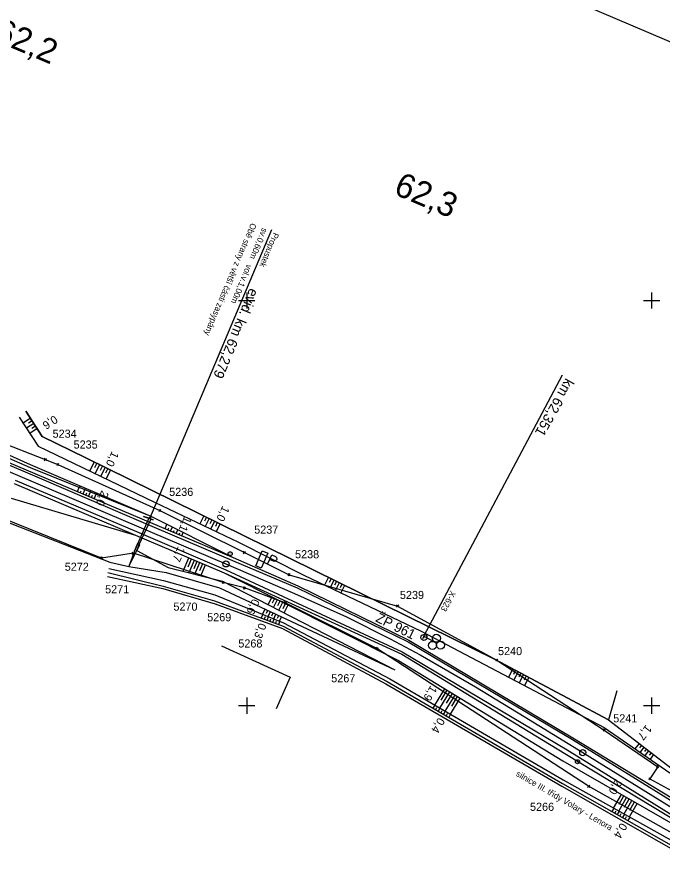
# Model space of a CAD drawing. Extents: x -805636 to -804553, y -1165340 to -1164656.
# Drawn here: x -805256.7 to -805097.2, y -1165040.5 to -1164830.1 of the extents above; entities that cross this region are included whole.
import ezdxf

# ---------------------------------------------------------------- set-up
doc = ezdxf.new("R2010")
doc.units = 0
for name, color, linetype in [('0381KM061-064P - Vrstva 1', 7, 'Continuous'), ('0381KM061-064P - Vrstva 17', 7, 'Continuous'), ('0381KM061-064P - Vrstva 19', 7, 'Continuous'), ('0381KM061-064P - Vrstva 23', 7, 'Continuous'), ('0381KM061-064P - Vrstva 33', 7, 'Continuous'), ('0381KM061-064P - Vrstva 4', 7, 'Continuous'), ('0381KM061-064P - Vrstva 48', 7, 'Continuous'), ('0381KM061-064P - Vrstva 49', 7, 'Continuous'), ('0381KM061-064P - Vrstva 51', 7, 'Continuous'), ('0381KM061-064P - Vrstva 7', 7, 'Continuous'), ('0381KM061-064P - Vrstva 8', 7, 'Continuous'), ('formát', 7, 'Continuous'), ('krizky_1000 - Vrstva 1', 7, 'Continuous'), ('szdc - hran DP', 7, 'Continuous'), ('szdc - szdc_cislo', 7, 'Continuous'), ('szdc - szdc_krizek', 7, 'Continuous'), ('vyt_sit - stávající', 7, 'Continuous')]:
    doc.layers.add(name, color=color, linetype=linetype)

msp = doc.modelspace()

# ---------------------------------------------------------------- linework, layer by layer
at = {"layer": '0381KM061-064P - Vrstva 1'}
for points in [[(-805344.65, -1164905.78), (-805313.66, -1164918.88), (-805286.17, -1164930.55), (-805256.63, -1164943.09), (-805230.48, -1164954.2), (-805205.12, -1164965.01), (-805202.66, -1164966.06)], [(-805202.66, -1164966.06), (-805188.16, -1164972.33), (-805175.38, -1164978.12)], [(-805175.38, -1164978.12), (-805164.58, -1164983.51), (-805157.2, -1164987.48)], [(-805157.2, -1164987.48), (-805143.51, -1164995.39), (-805131.47, -1165002.7)], [(-805131.47, -1165002.7), (-805117.01, -1165011.6), (-805094.55, -1165025.46), (-805076.19, -1165036.77)]]:
    msp.add_lwpolyline(points, dxfattribs=at)
at = {"layer": '0381KM061-064P - Vrstva 17'}
msp.add_lwpolyline([(-805108.59, -1164996.37), (-805110.66, -1165003.53), (-805138.64, -1164988.6), (-805160.38, -1164977.95), (-805217.98, -1164949.5), (-805239.73, -1164938.85), (-805250.48, -1164933.58), (-805254.52, -1164927.32)], dxfattribs=at)
at = {"layer": '0381KM061-064P - Vrstva 19'}
msp.add_line((-805223.94, -1164953.85), (-805193.79, -1164882.51), dxfattribs=at)
for points in [[(-805225.46, -1164953.29), (-805223.07, -1164954.18)], [(-805223.07, -1164954.18), (-805223.66, -1164953.94), (-805223.66, -1164953.95), (-805224.21, -1164953.74), (-805224.2, -1164953.73), (-805225.46, -1164953.29), (-805225.46, -1164953.29)], [(-805224.2, -1164953.73), (-805226.95, -1164960.17)], [(-805223.66, -1164953.94), (-805226.63, -1164960.32)], [(-805226.95, -1164960.17), (-805227.7, -1164961.91), (-805226.89, -1164959.92)], [(-805226.63, -1164960.32), (-805227.14, -1164961.71), (-805226.51, -1164960.3)], [(-805226.95, -1164960.17), (-805226.89, -1164959.92), (-805226.51, -1164960.3), (-805226.63, -1164960.32)]]:
    msp.add_lwpolyline(points, dxfattribs=at)
at = {"layer": '0381KM061-064P - Vrstva 23'}
msp.add_lwpolyline([(-805206.24, -1164985.26), (-805189.29, -1164992.96), (-805192.75, -1165000.8)], dxfattribs=at)
at = {"layer": '0381KM061-064P - Vrstva 33'}
msp.add_lwpolyline([(-805196.16, -1164961.8), (-805194.79, -1164962.4), (-805196.4, -1164966.09), (-805197.77, -1164965.49)], close=True, dxfattribs=at)
for points in [[(-805194.83, -1164965.11), (-805193.83, -1164962.81)], [(-805193.37, -1164964.36), (-805194.33, -1164963.94)], [(-805193.83, -1164962.81), (-805192.88, -1164963.22)], [(-805192.88, -1164963.22), (-805192.63, -1164963.45), (-805192.59, -1164963.91), (-805192.68, -1164964.11), (-805193.04, -1164964.4), (-805193.37, -1164964.36)]]:
    msp.add_lwpolyline(points, dxfattribs=at)
at = {"layer": '0381KM061-064P - Vrstva 4'}
for points in [[(-805364.7, -1164895.97), (-805343.19, -1164904.86), (-805317.03, -1164915.68), (-805296.75, -1164924.42), (-805284.83, -1164929.56), (-805254.7, -1164942.26), (-805226.16, -1164954.55), (-805203.52, -1164964.18), (-805187.57, -1164970.92)], [(-805364.7, -1164895.97), (-805342.91, -1164904.36), (-805316.81, -1164915.12), (-805296.46, -1164924.13), (-805284.52, -1164929.13), (-805254.45, -1164941.83), (-805225.92, -1164953.93), (-805203.38, -1164963.47), (-805187.4, -1164970.45)], [(-805257.21, -1164944.39), (-805227.21, -1164957.06), (-805205.17, -1164966.48), (-805161.59, -1164986.72), (-805120.84, -1165010.88), (-805082.03, -1165034.98)], [(-805257.4, -1164945.18), (-805227.5, -1164957.9), (-805205.55, -1164967.2), (-805161.7, -1164987.26), (-805121.4, -1165011.84), (-805082.08, -1165035.58)], [(-805187.57, -1164970.92), (-805160.12, -1164984.24), (-805119.58, -1165008.37), (-805080.47, -1165032.5)], [(-805187.4, -1164970.45), (-805159.98, -1164983.82), (-805119.44, -1165007.96), (-805080.11, -1165031.8)]]:
    msp.add_lwpolyline(points, dxfattribs=at)
at = {"layer": '0381KM061-064P - Vrstva 48'}
for p, q in [((-805253.38, -1164929.09), (-805255.23, -1164930.29)), ((-805252.97, -1164929.72), (-805253.9, -1164930.32)), ((-805252.57, -1164930.35), (-805254.41, -1164931.54)), ((-805251.75, -1164931.61), (-805253.59, -1164932.8)), ((-805252.16, -1164930.99), (-805253.08, -1164931.58)), ((-805237.68, -1164939.86), (-805238.76, -1164942.09)), ((-805237, -1164940.19), (-805237.55, -1164941.3)), ((-805236.33, -1164940.52), (-805237.41, -1164942.74)), ((-805235.65, -1164940.85), (-805236.2, -1164941.96)), ((-805234.98, -1164941.18), (-805236.06, -1164943.39)), ((-805234.31, -1164941.51), (-805234.85, -1164942.61)), ((-805233.63, -1164941.84), (-805234.71, -1164944.04)), ((-805241.79, -1164947.2), (-805241.34, -1164946.12)), ((-805241.16, -1164945.74), (-805241.33, -1164946.13)), ((-805241.1, -1164947.49), (-805240.87, -1164946.95)), ((-805240.47, -1164946.04), (-805240.55, -1164946.22)), ((-805240.41, -1164947.78), (-805239.95, -1164946.69)), ((-805239.78, -1164946.33), (-805239.94, -1164946.69)), ((-805239.09, -1164946.63), (-805239.17, -1164946.8)), ((-805238.4, -1164946.93), (-805238.54, -1164947.25)), ((-805239.72, -1164948.07), (-805239.48, -1164947.52)), ((-805239.03, -1164948.37), (-805238.55, -1164947.25)), ((-805238.34, -1164948.66), (-805238.1, -1164948.09)), ((-805237.71, -1164947.22), (-805237.78, -1164947.38)), ((-805237.65, -1164948.95), (-805237.16, -1164947.8)), ((-805237.03, -1164947.52), (-805237.15, -1164947.81)), ((-805210.62, -1164953.13), (-805211.59, -1164955.1)), ((-805209.95, -1164953.46), (-805210.43, -1164954.44)), ((-805220.17, -1164956.36), (-805219.7, -1164955.24)), ((-805209.27, -1164953.79), (-805210.24, -1164955.75)), ((-805208.6, -1164954.13), (-805209.08, -1164955.1)), ((-805207.93, -1164954.46), (-805208.88, -1164956.39)), ((-805207.26, -1164954.79), (-805207.73, -1164955.75)), ((-805206.58, -1164955.12), (-805207.53, -1164957.04)), ((-805219.48, -1164956.65), (-805219.26, -1164956.11)), ((-805218.79, -1164956.94), (-805218.36, -1164955.91)), ((-805218.1, -1164957.23), (-805217.89, -1164956.74)), ((-805217.41, -1164957.53), (-805217.02, -1164956.59)), ((-805216.72, -1164957.82), (-805216.53, -1164957.37)), ((-805216.03, -1164958.11), (-805215.67, -1164957.27)), ((-805215.72, -1164966.81), (-805214.31, -1164963.49)), ((-805214.44, -1164965.71), (-805213.62, -1164963.78)), ((-805214.25, -1164967.18), (-805212.93, -1164964.07)), ((-805213, -1164966.17), (-805212.24, -1164964.37)), ((-805212.78, -1164967.55), (-805211.55, -1164964.66)), ((-805211.57, -1164966.63), (-805210.86, -1164964.95)), ((-805211.31, -1164967.93), (-805210.17, -1164965.24)), ((-805179.84, -1164968.33), (-805180.79, -1164970.25)), ((-805179.17, -1164968.67), (-805179.64, -1164969.62)), ((-805178.5, -1164969), (-805179.43, -1164970.9)), ((-805177.82, -1164969.33), (-805178.29, -1164970.27)), ((-805177.15, -1164969.66), (-805178.08, -1164971.54)), ((-805176.48, -1164970), (-805176.94, -1164970.93)), ((-805175.81, -1164970.33), (-805176.72, -1164972.18)), ((-805194.72, -1164975.07), (-805193.75, -1164973.14)), ((-805193.67, -1164974.64), (-805193.08, -1164973.48)), ((-805193.39, -1164975.75), (-805192.41, -1164973.81)), ((-805192.33, -1164975.32), (-805191.74, -1164974.15)), ((-805192.05, -1164976.44), (-805191.07, -1164974.49)), ((-805196.08, -1164977.43), (-805195.48, -1164976.15)), ((-805195.15, -1164977.21), (-805194.8, -1164976.47)), ((-805190.99, -1164976), (-805190.4, -1164974.83)), ((-805190.72, -1164977.12), (-805189.73, -1164975.16)), ((-805196.04, -1164977.44), (-805196.4, -1164978.43)), ((-805195.48, -1164978.11), (-805195.7, -1164978.69)), ((-805194.65, -1164978), (-805194.99, -1164978.95)), ((-805194.69, -1164977.99), (-805194.12, -1164976.79)), ((-805194.09, -1164978.65), (-805194.29, -1164979.21)), ((-805193.77, -1164977.8), (-805193.45, -1164977.11)), ((-805193.25, -1164978.56), (-805193.59, -1164979.47)), ((-805193.29, -1164978.55), (-805192.77, -1164977.42)), ((-805192.39, -1164978.4), (-805192.09, -1164977.74)), ((-805191.9, -1164979.11), (-805191.41, -1164978.06)), ((-805192.69, -1164979.2), (-805192.89, -1164979.73)), ((-805191.86, -1164979.13), (-805192.18, -1164979.99)), ((-805134.27, -1164990.93), (-805135.34, -1164992.94)), ((-805133.61, -1164991.28), (-805134.14, -1164992.29)), ((-805132.95, -1164991.64), (-805134.02, -1164993.64)), ((-805132.29, -1164991.99), (-805132.82, -1164992.99)), ((-805131.62, -1164992.34), (-805132.69, -1164994.34)), ((-805130.96, -1164992.7), (-805131.49, -1164993.69)), ((-805130.3, -1164993.05), (-805131.36, -1164995.04)), ((-805153.57, -1164999.86), (-805151.11, -1164995.82)), ((-805152.28, -1165000.61), (-805149.83, -1164996.6)), ((-805151.94, -1164998.63), (-805150.47, -1164996.21)), ((-805150.98, -1165001.37), (-805148.55, -1164997.38)), ((-805150.65, -1164999.39), (-805149.19, -1164996.99)), ((-805149.69, -1165002.12), (-805147.27, -1164998.16)), ((-805149.36, -1165000.16), (-805147.91, -1164997.77)), ((-805153.56, -1164999.87), (-805154, -1165000.63)), ((-805153.09, -1165000.55), (-805153.35, -1165001.01)), ((-805152.27, -1165000.62), (-805152.71, -1165001.38)), ((-805151.79, -1165001.3), (-805152.06, -1165001.76)), ((-805150.97, -1165001.38), (-805151.41, -1165002.14)), ((-805150.5, -1165002.06), (-805150.76, -1165002.51)), ((-805149.67, -1165002.13), (-805150.11, -1165002.89)), ((-805103.12, -1165009.34), (-805104.11, -1165010.63)), ((-805102.52, -1165009.79), (-805103.01, -1165010.42)), ((-805101.93, -1165010.25), (-805102.87, -1165011.48)), ((-805101.33, -1165010.71), (-805101.8, -1165011.31)), ((-805100.74, -1165011.17), (-805101.64, -1165012.33)), ((-805100.14, -1165011.62), (-805100.58, -1165012.19)), ((-805099.55, -1165012.08), (-805100.4, -1165013.19)), ((-805109.42, -1165025.28), (-805107.48, -1165021.9)), ((-805108.11, -1165026.01), (-805106.18, -1165022.64)), ((-805107.99, -1165024.3), (-805106.83, -1165022.27)), ((-805106.8, -1165026.74), (-805104.88, -1165023.39)), ((-805106.69, -1165025.03), (-805105.53, -1165023.01)), ((-805105.49, -1165027.48), (-805103.58, -1165024.13)), ((-805105.38, -1165025.77), (-805104.23, -1165023.76)), ((-805109.35, -1165025.32), (-805109.81, -1165026.13)), ((-805108.88, -1165026.01), (-805109.15, -1165026.5)), ((-805108.04, -1165026.05), (-805108.5, -1165026.86)), ((-805107.57, -1165026.74), (-805107.85, -1165027.23)), ((-805106.73, -1165026.78), (-805107.2, -1165027.6)), ((-805106.27, -1165027.48), (-805106.54, -1165027.97)), ((-805105.42, -1165027.51), (-805105.89, -1165028.34))]:
    msp.add_line(p, q, dxfattribs=at)
at = {"layer": '0381KM061-064P - Vrstva 49'}
for p, q in [((-805225.92, -1164953.93), (-805203.38, -1164963.47)), ((-805227.5, -1164957.9), (-805205.55, -1164967.2))]:
    msp.add_line(p, q, dxfattribs=at)
for points in [[(-805295.94, -1164922.85), (-805284.04, -1164927.86), (-805253.46, -1164941.25), (-805223.68, -1164953.23)], [(-805295.19, -1164922.01), (-805283.65, -1164926.95), (-805253.5, -1164940.46), (-805223.68, -1164953.23)], [(-805296.46, -1164924.13), (-805284.52, -1164929.13), (-805254.45, -1164941.83), (-805225.92, -1164953.93)], [(-805254.52, -1164927.32), (-805250.48, -1164933.58), (-805239.73, -1164938.85), (-805217.98, -1164949.5), (-805160.38, -1164977.95), (-805138.64, -1164988.6), (-805110.66, -1165003.53), (-805077.76, -1165028.83)], [(-805256.22, -1164928.77), (-805251.54, -1164935.95), (-805222.74, -1164949.79)], [(-805258.14, -1164948.79), (-805227.5, -1164957.9)], [(-805222.74, -1164949.79), (-805202.04, -1164959.65), (-805185.93, -1164967.81)], [(-805223.66, -1164953.94), (-805223.07, -1164954.18), (-805225.46, -1164953.29), (-805225.46, -1164953.29), (-805224.2, -1164953.73)], [(-805223.66, -1164953.94), (-805223.68, -1164953.23), (-805224.2, -1164953.73)], [(-805223.68, -1164953.23), (-805203.38, -1164963.47)], [(-805259.86, -1164954.37), (-805233.78, -1164964.57)], [(-805227.7, -1164961.91), (-805229.15, -1164965.65), (-805227.14, -1164961.71)], [(-805227.7, -1164961.91), (-805226.89, -1164959.92), (-805226.51, -1164960.3), (-805227.14, -1164961.71)], [(-805227.14, -1164961.71), (-805219.41, -1164965.87), (-805205.96, -1164969.29)], [(-805233.78, -1164964.57), (-805229.15, -1164965.65)], [(-805229.15, -1164965.65), (-805219.86, -1164967.18), (-805206.69, -1164970.91), (-805163.45, -1164991.14)], [(-805234.27, -1164967.17), (-805220.67, -1164970.52), (-805207.94, -1164974.16), (-805191.02, -1164980.42), (-805165.29, -1164994.07), (-805122, -1165019.23), (-805085.43, -1165039.91)], [(-805234.06, -1164966.19), (-805220.55, -1164969.15), (-805207.89, -1164972.65), (-805190.88, -1164979.53), (-805164.65, -1164993.41), (-805121.85, -1165018.34), (-805084.74, -1165039.06)], [(-805205.55, -1164967.2), (-805162.48, -1164988.88), (-805121.89, -1165013.64), (-805082.35, -1165036.29)], [(-805185.93, -1164967.81), (-805156.92, -1164981.59), (-805111.71, -1165005.38), (-805077.76, -1165028.83)], [(-805205.96, -1164969.29), (-805163.45, -1164991.14)]]:
    msp.add_lwpolyline(points, dxfattribs=at)
at = {"layer": '0381KM061-064P - Vrstva 51'}
msp.add_lwpolyline([(-805234.38, -1164968.09), (-805220.73, -1164971.11), (-805207.78, -1164974.89), (-805191.18, -1164980.95), (-805165.61, -1164994.58), (-805122.14, -1165019.85), (-805085.93, -1165040.55)], dxfattribs=at)
at = {"layer": '0381KM061-064P - Vrstva 7'}
for p, q in [((-805204.14, -1164962.5), (-805204.05, -1164962.54)), ((-805118.35, -1165013.81), (-805118.26, -1165013.86))]:
    msp.add_line(p, q, dxfattribs=at)
for centre, radius in [((-805204.09, -1164962.52), 0.5), ((-805205.12, -1164965.01), 0.75), ((-805117.01, -1165011.6), 0.75), ((-805118.3, -1165013.84), 0.5)]:
    msp.add_circle(centre, radius, dxfattribs=at)
at = {"layer": '0381KM061-064P - Vrstva 8'}
for p, q in [((-805156.26, -1164982.82), (-805122, -1164918.34)), ((-805155.9, -1164982.16), (-805156.62, -1164983.48)), ((-805156.26, -1164982.82), (-805153.62, -1164984.25))]:
    msp.add_line(p, q, dxfattribs=at)
for centre in [(-805153.15, -1164983.37), (-805154.1, -1164985.13), (-805152.13, -1164985.06)]:
    msp.add_circle(centre, 1, dxfattribs=at)
at = {"layer": 'formát'}
msp.add_line((-804939.6, -1164902.47), (-805519.31, -1164655.82), dxfattribs=at)
at = {"layer": 'krizky_1000 - Vrstva 1'}
for points in [[(-805200, -1164898), (-805200, -1164902)], [(-805100, -1164898), (-805100, -1164902)], [(-805202, -1164900), (-805198, -1164900)], [(-805102, -1164900), (-805098, -1164900)], [(-805200, -1164998), (-805200, -1165002)], [(-805100, -1164998), (-805100, -1165002)], [(-805202, -1165000), (-805198, -1165000)], [(-805102, -1165000), (-805098, -1165000)]]:
    msp.add_lwpolyline(points, dxfattribs=at)
at = {"layer": 'szdc - hran DP'}
for p, q in [((-805367.78, -1164893.1), (-805249.75, -1164939.24)), ((-805249.75, -1164939.24), (-805246.66, -1164940.48)), ((-805246.66, -1164940.48), (-805221.45, -1164951.84)), ((-805235.86, -1164963.58), (-805268.35, -1164950.48)), ((-805221.45, -1164951.84), (-805200.57, -1164962.2)), ((-805227.98, -1164962.4), (-805235.86, -1164963.58)), ((-805205.81, -1164969.6), (-805227.98, -1164962.4)), ((-805200.57, -1164962.2), (-805189.53, -1164967.68)), ((-805189.53, -1164967.68), (-805162.72, -1164975.42)), ((-805200.52, -1164970.95), (-805205.81, -1164969.6)), ((-805190.48, -1164974.63), (-805200.52, -1164970.95)), ((-805167.83, -1164985.89), (-805190.48, -1164974.63)), ((-805162.72, -1164975.42), (-805138.24, -1164988.78)), ((-805115.56, -1165019.91), (-805167.83, -1164985.89)), ((-805138.24, -1164988.78), (-805111.69, -1165006.01)), ((-805111.69, -1165006.01), (-805098.46, -1165015.06)), ((-805098.46, -1165015.06), (-805100.45, -1165018.04)), ((-805100.45, -1165018.04), (-805061.96, -1165039.19)), ((-805085.48, -1165036.81), (-805115.56, -1165019.91))]:
    msp.add_line(p, q, dxfattribs=at)
at = {"layer": 'szdc - szdc_krizek'}
for p, q in [((-805249.48, -1164939.51), (-805250.02, -1164938.98)), ((-805250.02, -1164939.51), (-805249.48, -1164938.98)), ((-805246.4, -1164940.75), (-805246.93, -1164940.22)), ((-805246.93, -1164940.75), (-805246.4, -1164940.22)), ((-805221.19, -1164952.1), (-805221.72, -1164951.57)), ((-805221.72, -1164952.1), (-805221.19, -1164951.57)), ((-805235.59, -1164963.84), (-805236.13, -1164963.31)), ((-805236.13, -1164963.84), (-805235.59, -1164963.31)), ((-805227.71, -1164962.67), (-805228.25, -1164962.14)), ((-805228.25, -1164962.67), (-805227.71, -1164962.14)), ((-805200.31, -1164962.47), (-805200.84, -1164961.94)), ((-805200.84, -1164962.47), (-805200.31, -1164961.94)), ((-805189.27, -1164967.95), (-805189.8, -1164967.42)), ((-805189.8, -1164967.95), (-805189.27, -1164967.42)), ((-805205.55, -1164969.86), (-805206.08, -1164969.33)), ((-805206.08, -1164969.86), (-805205.55, -1164969.33)), ((-805200.26, -1164971.22), (-805200.79, -1164970.69)), ((-805200.79, -1164971.22), (-805200.26, -1164970.69)), ((-805190.21, -1164974.9), (-805190.75, -1164974.36)), ((-805190.75, -1164974.9), (-805190.21, -1164974.36)), ((-805162.46, -1164975.69), (-805162.99, -1164975.16)), ((-805162.99, -1164975.69), (-805162.46, -1164975.16)), ((-805167.57, -1164986.16), (-805168.1, -1164985.62)), ((-805168.1, -1164986.16), (-805167.57, -1164985.62)), ((-805137.97, -1164989.04), (-805138.51, -1164988.52)), ((-805138.51, -1164989.04), (-805137.97, -1164988.52)), ((-805111.43, -1165006.28), (-805111.96, -1165005.75)), ((-805111.96, -1165006.28), (-805111.43, -1165005.75)), ((-805098.2, -1165015.32), (-805098.73, -1165014.79)), ((-805098.73, -1165015.32), (-805098.2, -1165014.79)), ((-805100.19, -1165018.3), (-805100.72, -1165017.78)), ((-805100.72, -1165018.3), (-805100.19, -1165017.78)), ((-805115.3, -1165020.18), (-805115.83, -1165019.65)), ((-805115.83, -1165020.18), (-805115.3, -1165019.65))]:
    msp.add_line(p, q, dxfattribs=at)
at = {"layer": 'vyt_sit - stávající'}
msp.add_line((-805156.29, -1164983.15), (-805156.2, -1164983.2), dxfattribs=at)
msp.add_circle((-805156.24, -1164983.18), 0.756, dxfattribs=at)

# ---------------------------------------------------------------- texts
at = {"layer": '0381KM061-064P - Vrstva 19'}
for s, height, rotation, p in [('Obě strany z větší části zasypány', 1.5, 247.0922, (-805198.9, -1164880.77)), ('sv.0,60m   vol.v.1,00m', 1.5, 247.0922, (-805196.13, -1164881.94)), ('Propustek', 1.5, 247.0922, (-805193.37, -1164883.11)), ('evid. km 62,279', 2.5, 247.4086, (-805199.25, -1164896.81))]:
    msp.add_text(s, height=height, rotation=rotation, dxfattribs=at).set_placement(p)
at = {"layer": '0381KM061-064P - Vrstva 48'}
for s, rotation, p in [('0,6', 212.8254, (-805247.5, -1164928.26)), ('1,0', 243.9354, (-805233.24, -1164937.05)), ('2,0', 247.0311, (-805235.82, -1164946.75)), ('1,0', 243.7126, (-805205.92, -1164950.56)), ('1,1', 247.0544, (-805215.37, -1164953.11)), ('1,7', 247.0407, (-805216.94, -1164960.55)), ('0,6', 244.9302, (-805198.51, -1164973.47)), ('0,3', 249.7019, (-805196.93, -1164979.45)), ('1,9', 238.6155, (-805154.54, -1164994.87)), ('0,4', 239.8316, (-805152.65, -1165002.8)), ('1,7', 232.4407, (-805101.35, -1165004.58)), ('2,0', 240.1974, (-805108.86, -1165017.97)), ('0,4', 240.5094, (-805107.62, -1165028.78))]:
    msp.add_text(s, height=2, rotation=rotation, dxfattribs=at).set_placement(p)
at = {"layer": '0381KM061-064P - Vrstva 51'}
msp.add_text('silnice III. třídy Volary - Lenora', height=1.5, rotation=329.8239, dxfattribs=at).set_placement((-805133.64, -1165017.24))
at = {"layer": '0381KM061-064P - Vrstva 7'}
for s, rotation, p in [('62,2', 337.0034, (-805262.71, -1164835.71)), ('62,3', 336.9207, (-805163.97, -1164873.65))]:
    msp.add_text(s, height=6, rotation=rotation, dxfattribs=at).set_placement(p)
at = {"layer": '0381KM061-064P - Vrstva 8'}
for s, height, rotation, p in [('km 62,351', 2.5, 240.4167, (-805121.2, -1164919.01)), ('X-623', 1.5, 241.514, (-805149.6, -1164971.53))]:
    msp.add_text(s, height=height, rotation=rotation, dxfattribs=at).set_placement(p)
at = {"layer": 'szdc - szdc_cislo'}
for s, p in [('5234', (-805247.94, -1164933.88)), ('5235', (-805242.75, -1164936.56)), ('5236', (-805219.15, -1164948.24)), ('5237', (-805198.15, -1164957.56)), ('5238', (-805188.06, -1164963.63)), ('5272', (-805244.94, -1164966.71)), ('5271', (-805234.97, -1164972.29)), ('5239', (-805162.16, -1164973.68)), ('5270', (-805218.1, -1164976.56)), ('5269', (-805209.76, -1164979.18)), ('5268', (-805202.07, -1164985.65)), ('5240', (-805137.94, -1164987.53)), ('5267', (-805179.12, -1164994.24)), ('5241', (-805109.49, -1165004.13)), ('5266', (-805130.04, -1165025.96))]:
    msp.add_text(s, height=2, dxfattribs=at).set_placement(p)
at = {"layer": 'vyt_sit - stávající'}
msp.add_text('ŽP 961', height=2.4, rotation=333.5611, dxfattribs=at).set_placement((-805168.35, -1164979.13))

doc.saveas('drawing.dxf')
